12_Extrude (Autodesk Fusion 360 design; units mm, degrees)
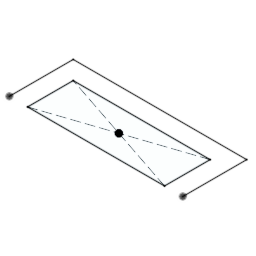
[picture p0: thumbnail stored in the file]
part number: 2026-07-16-12-28-49-690
sketch "Sketch1" plane through (0, 0, 0) normal (0, 0, 1) x axis (1, 0, 0)
  line L1 (-37.5, -12.5) -> (37.5, -12.5)
  line L2 (-37.5, 12.5) -> (-37.5, -12.5)
  line L3 (37.5, 12.5) -> (-37.5, 12.5)
  line L4 (37.5, -12.5) -> (37.5, 12.5)
  line L5 (-37.5, 12.5) -> (37.5, -12.5)
  line L6 (37.5, 12.5) -> (-37.5, -12.5)
  line L7 (-47.5, 22.5) -> (-47.5, -12.5)
  line L8 (47.5, 22.5) -> (-47.5, 22.5)
  line L9 (47.5, -12.5) -> (47.5, 22.5)
  point P6 (0, 0)
  point P1 (0, 0)
  point P2 (37.5, -12.5)
  point P10 (47.5, -12.5)
  point P3 (-37.5, -12.5)
  point P7 (-47.5, -12.5)
  point P4 (-37.5, 12.5)
  point P5 (37.5, 12.5)
  horizontal L1
  perpendicular L1 L2
  parallel L1 L3
  parallel L2 L4
  coincident L5 P6
  coincident L6 P6
  coincident P1 P6
  horizontal P2 P10
  horizontal P3 P7
  dimension "d1" distance P4 P5 = 75
  dimension "d2" distance P3 P4 = 25
  dimension "d3" = -10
